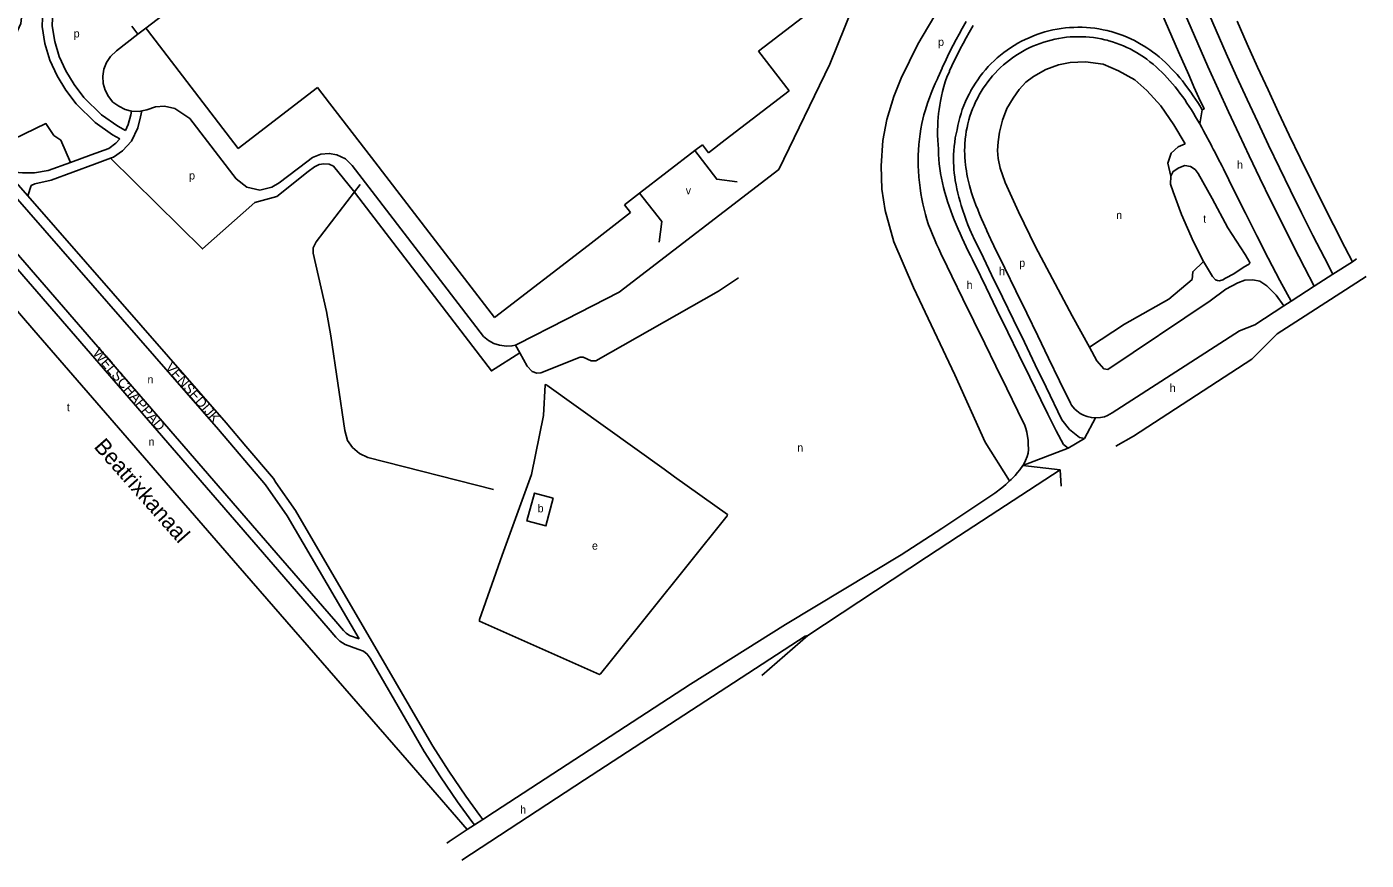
# Model space of a CAD drawing. Extents: x 155317 to 156514, y 385353 to 386894.
# Drawn here: x 155844 to 156514, y 385353 to 385769 of the extents above; entities that cross this region are included whole.
import ezdxf

# ---------------------------------------------------------------- set-up
doc = ezdxf.new("R2010")
doc.units = 0
for name, color, linetype in [('BLT_Basislijn', 7, 'Continuous'), ('BLT_Bebouwing', 7, 'Continuous'), ('BLT_Centroide', 7, 'Continuous'), ('BLT_Straatnaam', 7, 'Continuous'), ('BLT_Vlakafsluiter', 7, 'Continuous'), ('BLT_Waternaam_spoorwegen', 7, 'Continuous')]:
    doc.layers.add(name, color=color, linetype=linetype)

msp = doc.modelspace()

# ---------------------------------------------------------------- linework, layer by layer
at = {"layer": 'BLT_Basislijn'}
for p, q in [((155896.92, 385769.6), (155899.98, 385765.62)), ((155899.98, 385765.62), (155903.94, 385768.67)), ((155940.3, 385568.07), (155783.18, 385747.9)), ((155756.28, 385723.55), (155847.99, 385617.7)), ((155844.96, 385684.79), (155834.22, 385697.07)), ((156011.04, 385690.48), (156008.19, 385686.79)), ((155944.06, 385571.36), (155844.96, 385684.79)), ((156507.07, 385651.91), (156497.37, 385645.64)), ((156509.22, 385653.3), (156507.07, 385651.91)), ((156497.37, 385645.64), (156488.05, 385639.62)), ((156488.05, 385639.62), (156476.44, 385632.12)), ((155847.99, 385617.7), (155949.97, 385500)), ((156088.71, 385610.2), (156090.89, 385606.28)), ((156323.47, 385561.74), (156335.69, 385542.3)), ((156168.21, 385544.42), (156162.96, 385548.17))]:
    msp.add_line(p, q, dxfattribs=at)
for points in [[(156354.54, 385959.56), (156358.38, 385947.67), (156362.3, 385935.8), (156366.29, 385923.96), (156370.36, 385912.14), (156374.49, 385900.35), (156378.7, 385888.58), (156382.98, 385876.84), (156387.34, 385865.13), (156391.76, 385853.44), (156396.26, 385841.78), (156400.83, 385830.15), (156405.48, 385818.55), (156410.19, 385806.97), (156414.97, 385795.43), (156419.83, 385783.91), (156424.76, 385772.43), (156429.75, 385760.97), (156434.82, 385749.55), (156439.96, 385738.16), (156445.17, 385726.8), (156450.45, 385715.47)], [(156358.03, 385915.71), (156360.44, 385908.7), (156364.6, 385896.84), (156368.83, 385885.02), (156373.13, 385873.22), (156377.51, 385861.44), (156381.96, 385849.69), (156386.48, 385837.97), (156391.07, 385826.28), (156395.74, 385814.62), (156400.48, 385802.98), (156405.29, 385791.38), (156410.17, 385779.8), (156415.12, 385768.26), (156420.14, 385756.75), (156425.24, 385745.26), (156426.65, 385742.14), (156427.88, 385739.4), (156430.4, 385733.81), (156432.92, 385728.33), (156432.01, 385727.91)], [(156088.71, 385610.2), (156089.74, 385610.65), (156113.8, 385623.01), (156140.6, 385636.67), (156220.33, 385698.01), (156245.83, 385750.68), (156261.55, 385789.62), (156276.14, 385827.7), (156283.36, 385846.18)], [(156330.89, 385837.33), (156326.4, 385824.83), (156316.9, 385805.48), (156300.98, 385779.55), (156289.84, 385760.69), (156281.59, 385743.67), (156277.8, 385734.53), (156274.32, 385723.05), (156272.38, 385712.55), (156271.52, 385699.8), (156271.86, 385688.21), (156273.57, 385677.43), (156277.85, 385661.87), (156287.65, 385639.05), (156308.31, 385595.31), (156323.47, 385561.74)], [(155875.78, 385803.77), (155872.57, 385802.32), (155866, 385798.42), (155861.49, 385792.58), (155858.91, 385785.36), (155857.46, 385777.61), (155857.1, 385769.8), (155858.38, 385762.07), (155860.65, 385754.48), (155863.95, 385747.27), (155868.14, 385740.45), (155872.87, 385734.06), (155881.78, 385725.32), (155889.89, 385719.61), (155893.72, 385717.48)], [(155842.98, 385784.51), (155841.39, 385770.98), (155837.07, 385761.46), (155830.47, 385755.24), (155821.08, 385752.33), (155815.37, 385747.12), (155812.71, 385740.52), (155813.85, 385734.94), (155816.39, 385729.36), (155822.99, 385728.59), (155828.06, 385726.94), (155837.71, 385713.24), (155853.98, 385720.92), (155857.99, 385715.03), (155861.39, 385712.72), (155866.19, 385701.58)], [(155850.86, 385788.73), (155853.16, 385788.51), (155854.07, 385786.67), (155852.48, 385778.19), (155852.08, 385769.5), (155853.5, 385760.94), (155855.96, 385752.71), (155859.53, 385744.91), (155863.99, 385737.65), (155869.09, 385730.77), (155878.57, 385721.46), (155887.23, 385715.37), (155890.94, 385713.31)], [(156433.95, 385779.03), (156438.97, 385767.49), (156444.06, 385755.97), (156449.23, 385744.49), (156454.46, 385733.04), (156459.77, 385721.63), (156465.15, 385710.25), (156470.6, 385698.9), (156476.12, 385687.58), (156481.71, 385676.3), (156487.38, 385665.06), (156493.11, 385653.85), (156497.37, 385645.64)], [(156343.32, 385570.03), (156339.78, 385577.26), (156334.29, 385588.49), (156328.81, 385599.72), (156323.32, 385610.95), (156317.83, 385622.18), (156312.34, 385633.41), (156306.85, 385644.64), (156306.6, 385645.14), (156305.55, 385647.29), (156304.5, 385649.45), (156303.44, 385651.63), (156302.39, 385653.83), (156301.35, 385656.04), (156300.27, 385658.38), (156299.2, 385660.74), (156298.15, 385663.12), (156297.12, 385665.52), (156296.12, 385667.95), (156295.15, 385670.41), (156294.96, 385670.91), (156294.37, 385672.96), (156293.67, 385675.54), (156293.02, 385678.14), (156292.69, 385679.51), (156292.41, 385680.77), (156291.87, 385683.41), (156291.38, 385686.08), (156290.96, 385688.76), (156290.61, 385691.46), (156290.33, 385694.17), (156290.3, 385694.45), (156290.11, 385697.12), (156290, 385699.78), (156289.97, 385702.44), (156290.01, 385705.09), (156290.13, 385707.74), (156290.33, 385710.43), (156290.61, 385713.11), (156290.97, 385715.77), (156291.41, 385718.41), (156291.92, 385721.03), (156292.4, 385723.17), (156292.92, 385725.28), (156293.5, 385727.38), (156294.13, 385729.46), (156294.84, 385731.63), (156295.6, 385733.76), (156296.54, 385736.21), (156297.54, 385738.62), (156298.59, 385740.99), (156299.7, 385743.34), (156299.92, 385743.8), (156300.69, 385745.71), (156301.94, 385748.66), (156302.07, 385748.96), (156303.26, 385751.58), (156304.62, 385754.46), (156306.04, 385757.31), (156307.49, 385760.14), (156308.98, 385762.93), (156310.49, 385765.71), (156312.02, 385768.46), (156313.97, 385771.92)], [(156354.91, 385575.69), (156351.37, 385582.93), (156345.88, 385594.16), (156340.39, 385605.39), (156334.9, 385616.62), (156329.42, 385627.85), (156323.93, 385639.08), (156318.44, 385650.31), (156318.19, 385650.8), (156317.15, 385652.95), (156316.1, 385655.09), (156315.07, 385657.23), (156314.04, 385659.37), (156313.03, 385661.51), (156311.99, 385663.76), (156310.97, 385666), (156309.98, 385668.26), (156309.01, 385670.52), (156308.08, 385672.78), (156307.18, 385675.06), (156306.32, 385677.35), (156305.5, 385679.64), (156304.72, 385681.95), (156304.34, 385683.16), (156304, 385684.26), (156303.32, 385686.59), (156302.71, 385688.93), (156302.15, 385691.27), (156301.65, 385693.63), (156301.22, 385695.99), (156301.18, 385696.23), (156300.84, 385698.56), (156300.56, 385700.89), (156300.34, 385703.23), (156300.2, 385705.57), (156300.12, 385707.92), (156300.12, 385708.4), (156299.94, 385710.32), (156299.79, 385712.73), (156299.71, 385715.15), (156299.7, 385717.58), (156299.77, 385720.02), (156299.87, 385722.01), (156300.03, 385724.01), (156300.23, 385726.01), (156300.48, 385728.01), (156300.8, 385730.1), (156301.17, 385732.2), (156301.66, 385734.62), (156302.22, 385737.05), (156302.83, 385739.46), (156303.51, 385741.86), (156303.65, 385742.34), (156304.39, 385744.19), (156305.61, 385747.06), (156305.73, 385747.35), (156306.89, 385749.9), (156308.22, 385752.72), (156309.61, 385755.51), (156311.04, 385758.28), (156312.5, 385761.04), (156313.99, 385763.78), (156315.51, 385766.51), (156317.45, 385769.94)], [(156507.07, 385651.91), (156503.33, 385659.12), (156497.63, 385670.27), (156492, 385681.45), (156486.44, 385692.66), (156480.95, 385703.91), (156475.53, 385715.19), (156470.18, 385726.51), (156464.91, 385737.86), (156459.7, 385749.24), (156454.56, 385760.66), (156449.5, 385772.11)], [(155896.74, 385727.23), (155893.51, 385727.98), (155890.33, 385729.59), (155887.49, 385731.74), (155885.25, 385734.5), (155883.54, 385737.63), (155882.63, 385741.07), (155882.38, 385744.62), (155882.92, 385748.14), (155884.25, 385751.44), (155886.17, 385754.45), (155889.3, 385757.36), (155899.98, 385765.62)], [(156432.01, 385727.91), (156431.3, 385729.07), (156430.92, 385729.67), (156429.8, 385731.44), (156428.65, 385733.18), (156427.48, 385734.91), (156426.27, 385736.62), (156425.15, 385738.17), (156423.39, 385740.67), (156422.1, 385742.3), (156420.77, 385743.91), (156419.41, 385745.5), (156418.01, 385747.05), (156416.57, 385748.58), (156415.09, 385750.06), (156413.58, 385751.51), (156412.03, 385752.92), (156410.44, 385754.28), (156408.81, 385755.6), (156407.14, 385756.87), (156405.78, 385757.85), (156404.4, 385758.79), (156402.99, 385759.7), (156401.56, 385760.56), (156399.85, 385761.54), (156398.11, 385762.45), (156396.34, 385763.31), (156394.43, 385764.17), (156392.48, 385764.96), (156390.51, 385765.68), (156388.52, 385766.34), (156386.51, 385766.92), (156385.62, 385767.16), (156384.47, 385767.44), (156382.42, 385767.89), (156380.36, 385768.27), (156378.28, 385768.58), (156376.2, 385768.82), (156374.11, 385768.98), (156372.01, 385769.08), (156369.91, 385769.1), (156367.81, 385769.06), (156365.72, 385768.94), (156363.63, 385768.75), (156361.55, 385768.49), (156359.47, 385768.16), (156357.41, 385767.76), (156355.37, 385767.29), (156353.34, 385766.75), (156351.33, 385766.14), (156349.35, 385765.46), (156347.38, 385764.71), (156345.45, 385763.9), (156343.54, 385763.03), (156341.67, 385762.09), (156339.82, 385761.08), (156338.01, 385760.02), (156336.24, 385758.89), (156334.51, 385757.71), (156332.82, 385756.46), (156331.18, 385755.16), (156329.57, 385753.81), (156328.02, 385752.4), (156326.51, 385750.93), (156325.06, 385749.42), (156323.66, 385747.86), (156322.31, 385746.25), (156321.01, 385744.6), (156319.78, 385742.9), (156318.6, 385741.17), (156317.48, 385739.39), (156316.42, 385737.58), (156316.28, 385737.32), (156315.43, 385735.73), (156314.5, 385733.85), (156313.63, 385731.94), (156312.83, 385730), (156312.09, 385728.04), (156311.43, 385726.05), (156310.83, 385724.03), (156310.3, 385722), (156309.83, 385719.96), (156309.44, 385717.9), (156308.98, 385715.84), (156308.59, 385713.77), (156308.27, 385711.68), (156308.01, 385709.57), (156307.83, 385707.45), (156307.73, 385705.33), (156307.69, 385703.54), (156307.71, 385701.75), (156307.73, 385701.16), (156307.78, 385699.95), (156307.91, 385698.09), (156308.08, 385696.23), (156308.31, 385694.37), (156308.59, 385692.52), (156308.96, 385690.4), (156309.39, 385688.3), (156309.87, 385686.2), (156310.4, 385684.12), (156310.97, 385682.06), (156311.57, 385680), (156312.35, 385677.56), (156313.17, 385675.13), (156314.03, 385672.72), (156314.91, 385670.33), (156315.82, 385667.96), (156317.41, 385664.6), (156317.67, 385664.05), (156319.54, 385660.19), (156321.27, 385656.64), (156326.73, 385645.4), (156332.19, 385634.15), (156337.64, 385622.91), (156343.1, 385611.66), (156348.56, 385600.42), (156354.02, 385589.17), (156361.89, 385572.9)], [(156366.14, 385581.16), (156360.68, 385592.4), (156355.22, 385603.65), (156349.76, 385614.89), (156344.3, 385626.14), (156338.84, 385637.38), (156333.38, 385648.63), (156327.92, 385659.87), (156326.4, 385663.02), (156326.21, 385663.42), (156324.42, 385667.3), (156324.17, 385667.84), (156322.66, 385671.15), (156321.67, 385673.41), (156320.7, 385675.67), (156319.77, 385677.93), (156318.88, 385680.19), (156318.04, 385682.46), (156317.38, 385684.36), (156316.75, 385686.26), (156316.17, 385688.17), (156315.63, 385690.09), (156315.14, 385692.01), (156314.71, 385693.93), (156314.38, 385695.61), (156314.09, 385697.29), (156313.84, 385698.97), (156313.67, 385700.41), (156313.64, 385700.65), (156313.53, 385701.74), (156313.48, 385702.27), (156313.35, 385703.89), (156313.27, 385705.51), (156313.24, 385707.45), (156313.28, 385709.39), (156313.38, 385711.32), (156313.47, 385712.48), (156313.54, 385713.26), (156313.78, 385715.18), (156314.07, 385717.1), (156314.44, 385719), (156314.86, 385720.89), (156315.35, 385722.77), (156315.91, 385724.63), (156316.52, 385726.46), (156317.2, 385728.28), (156317.94, 385730.07), (156318.74, 385731.84), (156319.61, 385733.57), (156320.39, 385735.04), (156320.52, 385735.28), (156321.5, 385736.96), (156322.53, 385738.6), (156323.62, 385740.2), (156324.76, 385741.77), (156325.96, 385743.29), (156327.21, 385744.78), (156328.5, 385746.22), (156329.85, 385747.62), (156331.24, 385748.97), (156332.67, 385750.27), (156334.15, 385751.52), (156335.67, 385752.73), (156337.23, 385753.87), (156338.83, 385754.97), (156340.47, 385756.01), (156342.14, 385757), (156343.84, 385757.92), (156345.58, 385758.79), (156347.34, 385759.6), (156349.13, 385760.35), (156350.94, 385761.04), (156352.77, 385761.66), (156354.63, 385762.22), (156356.5, 385762.72), (156358.39, 385763.16), (156360.29, 385763.53), (156362.21, 385763.84), (156364.13, 385764.08), (156366.06, 385764.25), (156368, 385764.36), (156369.94, 385764.4), (156371.87, 385764.38), (156373.81, 385764.29), (156375.74, 385764.14), (156377.67, 385763.92), (156379.59, 385763.63), (156381.49, 385763.28), (156383.39, 385762.87), (156384.45, 385762.61), (156385.27, 385762.39), (156387.13, 385761.85), (156388.97, 385761.24), (156390.79, 385760.57), (156392.59, 385759.84), (156394.36, 385759.05), (156395.99, 385758.26), (156397.6, 385757.41), (156399.18, 385756.51), (156400.49, 385755.72), (156400.5, 385755.71), (156401.8, 385754.87), (156403.09, 385754), (156404.35, 385753.09), (156405.9, 385751.91), (156407.43, 385750.67), (156408.92, 385749.4), (156410.37, 385748.07), (156411.8, 385746.71), (156413.19, 385745.31), (156414.55, 385743.87), (156415.88, 385742.39), (156417.18, 385740.88), (156418.45, 385739.35), (156419.69, 385737.78), (156420.9, 385736.18), (156422.08, 385734.56), (156423.24, 385732.92), (156424.38, 385731.25), (156425.49, 385729.56), (156426.58, 385727.86), (156427.64, 385726.13), (156428.69, 385724.39), (156429.73, 385722.63), (156430.74, 385720.86)], [(156375.58, 385609.11), (156367.07, 385624.83), (156348.69, 385659.31), (156340.17, 385676.85), (156333.45, 385691.44), (156330.99, 385698.65), (156330.05, 385703.54), (156329.68, 385707.57), (156329.96, 385711.88), (156330.71, 385716.66), (156332.21, 385722.75), (156334.27, 385728.46), (156337.45, 385733.71), (156340.45, 385738.02), (156343.82, 385741.67), (156347.75, 385744.57), (156353.75, 385748.04), (156360.23, 385750.4), (156365.94, 385751.43), (156373.62, 385751.9), (156382.43, 385750.59), (156390.1, 385747.41), (156398.34, 385742.91), (156404.34, 385737.57), (156411.27, 385729.8), (156417.82, 385720.33), (156423.51, 385710.79)], [(156010.49, 385463.37), (156005.73, 385465.07), (156004.06, 385466.13), (156002.67, 385467.59), (155998.82, 385472.05), (155971.28, 385503.82), (155800.32, 385701.14), (155796.27, 385705.61), (155794.11, 385707.79), (155791.85, 385709.92), (155789.56, 385711.98), (155787.21, 385713.96), (155784.79, 385715.87), (155782.33, 385717.71), (155779.81, 385719.46), (155777.26, 385721.13), (155774.75, 385722.74), (155772.34, 385724.39), (155769.98, 385726.11), (155767.66, 385727.92), (155765.41, 385729.77), (155764.39, 385730.67)], [(155949.08, 385693.29), (155925.84, 385723.45), (155918.38, 385728.54), (155913.29, 385729.63), (155908.78, 385729.28), (155904.43, 385727.88), (155901.83, 385727.31)], [(155901.83, 385727.31), (155901.31, 385724.27), (155899.86, 385718.79), (155896.78, 385712.21), (155892.19, 385707.35), (155887.7, 385704.12), (155886.27, 385703.6)], [(155896.74, 385727.23), (155896.42, 385725.33), (155895.14, 385720.5), (155893.72, 385717.48)], [(155901.83, 385727.31), (155900.53, 385727.02), (155896.98, 385727.18), (155896.74, 385727.23)], [(156430.74, 385720.86), (156431.74, 385719.08), (156432.73, 385717.28), (156433.71, 385715.47), (156434.67, 385713.68), (156434.86, 385713.32), (156435.62, 385711.88), (156436.57, 385710.07), (156436.86, 385709.51), (156437.51, 385708.25), (156438.45, 385706.43), (156439.39, 385704.61), (156439.46, 385704.46), (156439.83, 385703.74), (156441.93, 385699.67), (156442.6, 385698.33), (156447.96, 385687.4), (156453.59, 385676.14), (156459.28, 385664.92), (156465.05, 385653.73), (156470.88, 385642.58), (156476.42, 385632.16)], [(155890.94, 385713.31), (155888.88, 385711.13), (155885.34, 385708.58), (155876.59, 385705.4), (155866.19, 385701.58)], [(156423.51, 385710.79), (156419.93, 385709.33), (156416.41, 385706.14), (156414.9, 385701.19), (156416.33, 385694.67)], [(156450.45, 385715.47), (156455.45, 385704.91), (156460.86, 385693.65), (156466.34, 385682.42), (156471.9, 385671.22), (156477.52, 385660.06), (156483.21, 385648.94), (156488.02, 385639.66)], [(155886.27, 385703.6), (155878.3, 385700.7), (155856.56, 385692.71), (155848.43, 385690.82), (155846.63, 385689.99), (155844.96, 385684.79)], [(155886.27, 385703.6), (155932.32, 385658.31), (155958.42, 385681.55)], [(155949.08, 385693.29), (155954.34, 385689.1), (155960.92, 385687.7), (155966.94, 385689.13), (155970.6, 385691.26), (155984.4, 385701.86), (155987.23, 385703.99), (155991.45, 385705.68), (155995.64, 385706.07), (155999.46, 385705.4), (156003.71, 385703.3), (156007.05, 385700.08), (156018.72, 385684.84), (156072.79, 385614.6), (156075.21, 385612.51), (156077.88, 385611.02), (156080.65, 385610.13), (156084.18, 385609.77), (156086.91, 385609.8), (156088.71, 385610.2)], [(156178.34, 385707.47), (156189.31, 385693.12), (156199.57, 385691.83)], [(156068.22, 385370.35), (156066.86, 385372.13), (156059.76, 385381.89), (156051.22, 385394.38), (156043.1, 385407.05), (156035.49, 385420.05), (156016.05, 385453.71), (156014.59, 385455.75), (156012.8, 385457.14), (156009.95, 385458.25), (156003.52, 385460.55), (156000.86, 385462.24), (155998.97, 385464.24), (155995.04, 385468.78), (155967.5, 385500.55), (155796.58, 385697.83)], [(155866.19, 385701.58), (155855.12, 385697.51), (155848.17, 385696.32), (155842.2, 385696.32), (155834.22, 385697.07)], [(155958.42, 385681.55), (155969.44, 385684.47), (155984.98, 385697.01), (155988.17, 385699.4), (155990.56, 385700.48), (155992.83, 385700.77), (155995.56, 385700.6), (155997.67, 385699.68), (156007.7, 385687.42), (156008.19, 385686.79)], [(156430, 385696.04), (156428.42, 385697.99), (156426.12, 385699.54), (156423.34, 385699.97), (156420.29, 385698.9), (156417.51, 385697.03), (156416.33, 385694.67)], [(156455.8, 385651.58), (156453.41, 385655.48), (156444.89, 385668.78), (156436.93, 385683.58), (156430, 385696.04)], [(156416.33, 385694.67), (156416.17, 385690.6), (156417.45, 385686.86), (156421.68, 385675.56), (156427.67, 385661.9), (156432.73, 385651.97)], [(156008.19, 385686.79), (155989.01, 385661.89), (155987.62, 385658.86), (155987.64, 385656.15), (155994.21, 385627.07), (155996.35, 385614.78), (156003.34, 385567.45), (156004.67, 385562.54), (156007.17, 385559.1), (156010.65, 385556.07), (156014.82, 385554.08), (156077.73, 385538.02)], [(156008.19, 385686.79), (156008.75, 385686.06), (156076.71, 385597.3), (156090.89, 385606.28)], [(156150.76, 385686.24), (156161.84, 385672.01), (156160.61, 385661.73)], [(156432.73, 385651.97), (156427.32, 385646.91), (156426.94, 385643.03), (156415.27, 385633.24), (156393.13, 385620.76), (156375.58, 385609.11)], [(156432.73, 385651.97), (156437.22, 385644.57), (156438.67, 385642.92), (156439.62, 385642.46), (156440.63, 385642.43), (156442.25, 385642.8), (156443.72, 385643.69), (156447.76, 385645.92), (156452.5, 385649.04), (156455.65, 385650.91)], [(156455.65, 385650.91), (156455.8, 385651.58)], [(156101.42, 385596.43), (156121.01, 385604.12), (156122.59, 385604.19), (156126.48, 385602.41), (156128.9, 385602.41), (156190.25, 385637.15), (156200.23, 385643.81)], [(156460.83, 385642.13), (156457.28, 385642.88), (156453.25, 385642.6), (156449.88, 385641.29), (156443.88, 385638.2), (156436.02, 385632.39), (156384.87, 385598.04), (156382.81, 385598.41), (156379.25, 385602.35), (156375.58, 385609.11)], [(156481.13, 385623.31), (156514, 385644.49)], [(156472.86, 385629.81), (156468.98, 385635.2), (156464.3, 385639.79), (156460.83, 385642.13)], [(156488.02, 385639.66), (156488.05, 385639.62)], [(156472.86, 385629.81), (156458.35, 385620.43), (156450.59, 385617.42), (156387.01, 385576.29), (156384.66, 385574.97), (156383.1, 385574.39), (156381.17, 385574.04), (156378.68, 385573.89)], [(156476.44, 385632.12), (156472.86, 385629.81)], [(156476.42, 385632.16), (156476.44, 385632.12)], [(156388.82, 385559.74), (156397.74, 385564.7), (156456.85, 385603.21), (156469.44, 385615.77), (156481.13, 385623.31)], [(156090.89, 385606.28), (156094.59, 385599.66), (156096.96, 385597.06), (156099.33, 385596.27), (156101.42, 385596.43)], [(156162.96, 385548.17), (156104.45, 385590.16), (156103.98, 385590.49), (156103.53, 385590.3), (156102.71, 385574.95), (156096.71, 385545.51), (156082.06, 385505.28), (156070.75, 385473.12), (156070.66, 385472.19), (156130.64, 385445.56), (156131.18, 385445.81), (156136.07, 385451.92)], [(156365.03, 385558.75), (156362.64, 385560.61), (156359.05, 385567.32), (156354.91, 385575.69)], [(156378.57, 385573.89), (156376.64, 385574.01), (156374.49, 385574.47), (156372.62, 385575.16), (156370.92, 385576.07), (156369.36, 385577.33), (156368.31, 385578.25), (156367.34, 385579.28), (156366.74, 385580.11), (156366.14, 385581.16)], [(155944.06, 385571.36), (155953.95, 385559.68)], [(156343.32, 385570.03), (156343.89, 385568.54), (156344.34, 385566.67), (156344.74, 385564.6), (156344.96, 385562.63), (156345.08, 385560.89), (156345.1, 385557.97), (156344.98, 385556.19), (156344.52, 385554.56), (156343.7, 385552.46), (156342.42, 385550.08)], [(156361.89, 385572.9), (156365.7, 385567.95), (156370.72, 385564.06), (156373.19, 385563.58)], [(156378.68, 385573.89), (156378.57, 385573.89)], [(155940.3, 385568.07), (155963.73, 385540.38), (155974.52, 385524.89), (156010.49, 385463.37)], [(156373.19, 385563.58), (156365.03, 385558.75)], [(155953.95, 385559.68), (155967.67, 385543.47), (155968.97, 385541.6)], [(156342.35, 385549.95), (156340.81, 385547.84), (156339.7, 385546.5), (156338.42, 385544.98), (156336.52, 385543.09), (156335.69, 385542.3)], [(156342.42, 385550.08), (156342.35, 385549.95)], [(156136.07, 385451.92), (156194.5, 385524.87), (156194.61, 385525.53), (156168.21, 385544.42)], [(156361.04, 385547.8), (156310.19, 385514.74), (156294.16, 385504.17), (156234.9, 385464.97)], [(156335.69, 385542.3), (156333.9, 385540.61), (156331.81, 385538.84), (156328.34, 385536.28), (156301.79, 385518.47), (156281.46, 385505.3)], [(155968.97, 385541.6), (155978.73, 385527.6), (156020.26, 385456.43)], [(156281.46, 385505.3), (156223.65, 385470.58), (156176.23, 385440.7), (156078.24, 385376.92), (156072.41, 385373.1)], [(155949.97, 385500), (156034.61, 385402.76), (156064.6, 385367.98)], [(156061.84, 385352.71), (156123.2, 385392.85), (156233.59, 385464.64), (156234.9, 385464.97)], [(156211.9, 385444.98), (156234.9, 385464.97)], [(156072.41, 385373.1), (156070.87, 385375.12), (156063.85, 385384.77), (156055.39, 385397.14), (156047.37, 385409.66), (156039.82, 385422.56), (156020.26, 385456.43)], [(156064.6, 385367.98), (156055.58, 385362.07), (156054.38, 385361.28)], [(156068.22, 385370.35), (156064.6, 385367.98)], [(156072.41, 385373.1), (156068.22, 385370.35)]]:
    msp.add_lwpolyline(points, dxfattribs=at)
at = {"layer": 'BLT_Bebouwing'}
for p, q in [((155939.8, 385796.26), (155903.94, 385768.67)), ((156210.26, 385757.19), (156245.95, 385784.61)), ((155903.94, 385768.67), (155904.66, 385767.73)), ((155904.66, 385767.73), (155950.15, 385708.56)), ((156225.51, 385737.36), (156210.26, 385757.19)), ((155950.15, 385708.56), (155989.81, 385739.02)), ((155989.81, 385739.02), (155995.78, 385731.24)), ((156193.6, 385712.85), (156225.51, 385737.36)), ((155995.78, 385731.24), (156016.66, 385704.05)), ((156178.34, 385707.47), (156182.17, 385710.41)), ((156182.17, 385710.41), (156185.21, 385706.4)), ((156185.21, 385706.4), (156193.6, 385712.85)), ((156016.66, 385704.05), (156047.11, 385664.48)), ((156150.76, 385686.24), (156178.34, 385707.47)), ((156143.17, 385680.41), (156150.76, 385686.24)), ((156125.02, 385660.09), (156146.12, 385676.56)), ((156146.12, 385676.56), (156143.17, 385680.41)), ((156047.11, 385664.48), (156078.18, 385624.09)), ((156078.18, 385624.09), (156125.02, 385660.09))]:
    msp.add_line(p, q, dxfattribs=at)
msp.add_lwpolyline([(156107.6, 385533.72), (156103.92, 385519.8), (156094.44, 385522.31), (156098.13, 385536.23), (156107.6, 385533.72)], dxfattribs=at)
at = {"layer": 'BLT_Vlakafsluiter'}
for p, q in [((156432.01, 385727.91), (156430.74, 385720.86)), ((156488.02, 385639.66), (156476.42, 385632.16)), ((156373.19, 385563.58), (156378.68, 385573.89)), ((156365.03, 385558.75), (156342.35, 385549.95)), ((156342.35, 385549.95), (156361.04, 385547.8)), ((156361.56, 385539.73), (156361.04, 385547.8))]:
    msp.add_line(p, q, dxfattribs=at)

# ---------------------------------------------------------------- texts
at = {"layer": 'BLT_Centroide'}
for s, p in [('p', (155867.84, 385764.01)), ('p', (156299.96, 385759.8)), ('h', (156449.4, 385698.38)), ('p', (155925.53, 385693)), ('v', (156173.81, 385685.57)), ('n', (156389, 385673.23)), ('t', (156432.49, 385671.41)), ('h', (156330.44, 385645.17)), ('p', (156340.52, 385649.32)), ('h', (156314.21, 385638.29)), ('n', (155904.72, 385591.06)), ('h', (156415.77, 385586.83)), ('t', (155864.39, 385577.16)), ('n', (155905.25, 385559.93)), ('n', (156229.57, 385557.02)), ('b', (156099.77, 385526.6)), ('e', (156126.94, 385507.96)), ('h', (156091.04, 385375.99))]:
    msp.add_text(s, height=4, dxfattribs=at).set_placement(p)
at = {"layer": 'BLT_Straatnaam'}
for s, rotation, p in [('WELSCHAPPAD', 310.19286, (155877.06, 385606.02)), ('VENSEDIJK', 311.1441, (155913.26, 385598.89))]:
    msp.add_text(s, height=5, rotation=rotation, dxfattribs=at).set_placement(p)
at = {"layer": 'BLT_Waternaam_spoorwegen'}
msp.add_text('Beatrixkanaal', height=8, rotation=311.4686, dxfattribs=at).set_placement((155877.58, 385559.19))

doc.saveas('drawing.dxf')
